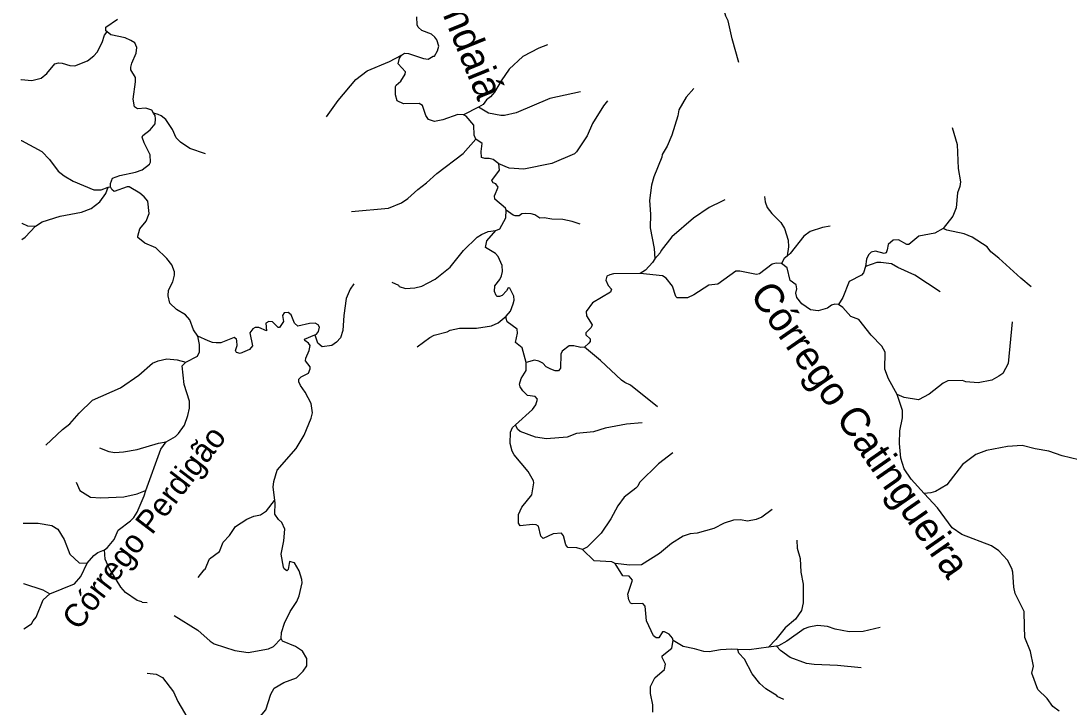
# Model space of a CAD drawing. Extents: x 393 to 446.6, y 8175.5 to 8231.
# Drawn here: x 393.18 to 400.42, y 8189.65 to 8194.39 of the extents above; entities that cross this region are included whole.
import ezdxf
from ezdxf.enums import TextEntityAlignment as Align

# ---------------------------------------------------------------- set-up
doc = ezdxf.new("R2010")
doc.units = 0
doc.header["$LTSCALE"] = 0.064
doc.linetypes.add('LONG_DASHED', pattern=[7.5, 6, -1.5])
doc.layers.add('61', color=7, linetype='Continuous')
doc.layers.add('7', color=7, linetype='Continuous', lineweight=25)
doc.layers.add('9', color=7, linetype='LONG_DASHED', lineweight=25)

msp = doc.modelspace()

# ---------------------------------------------------------------- linework, layer by layer
at = {"layer": '7'}
for p, q in [((396.3375, 8193.7957), (396.2359, 8193.7427)), ((393.7808, 8193.2408), (393.7972, 8193.2449)), ((398.3961, 8190.0715), (398.3408, 8190.0636))]:
    msp.add_line(p, q, dxfattribs=at)
for points in [[(393.7727, 8194.3151), (393.7638, 8194.322), (393.7638, 8194.3464), (393.8441, 8194.4029)], [(395.8073, 8194.1538), (395.8271, 8194.1666), (395.8561, 8194.1655), (395.9595, 8194.1316), (395.9918, 8194.1267), (396.0257, 8194.1461), (396.0354, 8194.1461), (396.0564, 8194.1833), (396.0644, 8194.2156), (396.0499, 8194.2608), (396.037, 8194.2785), (396.0128, 8194.2995), (395.9482, 8194.3254), (395.9207, 8194.348), (395.9159, 8194.3625), (395.9126, 8194.419)], [(393.1782, 8193.9868), (393.1792, 8193.9867), (393.18, 8193.9866), (393.2531, 8193.9782), (393.3177, 8193.9959), (393.3564, 8194.0282), (393.4114, 8194.0944), (393.4372, 8194.1009), (393.463, 8194.0993), (393.5147, 8194.0831), (393.5502, 8194.0799), (393.6374, 8194.1138), (393.6826, 8194.1493), (393.7052, 8194.1752), (393.7391, 8194.2414), (393.7553, 8194.2931), (393.7708, 8194.3127), (393.7727, 8194.3151)], [(394.0935, 8193.7537), (394.082, 8193.7727), (394.0411, 8193.7876), (393.983, 8193.7828), (393.962, 8193.7973), (393.9523, 8193.8506), (393.97, 8193.9701), (393.9684, 8193.9992), (393.9377, 8194.0525), (393.9377, 8194.0702), (393.9442, 8194.0993), (393.9749, 8194.1671), (393.9797, 8194.2059), (393.9636, 8194.2382), (393.9378, 8194.2559), (393.899, 8194.2737), (393.7989, 8194.2947), (393.7727, 8194.3151)], [(396.8147, 8194.2256), (396.7556, 8194.2026), (396.6442, 8194.1445), (396.5505, 8194.0573), (396.494, 8193.9766), (396.4487, 8193.8991), (396.4221, 8193.8655), (396.3942, 8193.8446), (396.3709, 8193.8132), (396.3375, 8193.7957)], [(395.289, 8193.7272), (395.3701, 8193.8409), (395.4912, 8193.9863), (395.5687, 8194.046), (395.7237, 8194.1106), (395.8073, 8194.1538)], [(396.2359, 8193.7427), (396.1951, 8193.7439), (396.0919, 8193.7069), (396.0337, 8193.6956), (395.9934, 8193.7101), (395.974, 8193.7376), (395.9514, 8193.807), (395.9288, 8193.8199), (395.8206, 8193.8183), (395.777, 8193.8377), (395.7657, 8193.8797), (395.7657, 8193.9378), (395.7689, 8193.9475), (395.8012, 8193.9749), (395.8319, 8194.0218), (395.8351, 8194.0396), (395.7835, 8194.0945), (395.7933, 8194.1329), (395.8073, 8194.1538)], [(397.0442, 8193.9016), (396.8315, 8193.8554), (396.599, 8193.7553), (396.5182, 8193.7359), (396.4923, 8193.7359), (396.4085, 8193.7537), (396.3394, 8193.7946), (396.3375, 8193.7957)], [(397.2303, 8193.838), (397.2023, 8193.8031), (397.1254, 8193.6811), (397.0882, 8193.5955), (397.0155, 8193.4857), (397.001, 8193.4727), (396.8444, 8193.4049), (396.6506, 8193.3662), (396.5505, 8193.3742), (396.4781, 8193.4036)], [(393.7972, 8193.2449), (393.796, 8193.267), (393.81, 8193.3031), (393.8602, 8193.3226), (393.9701, 8193.3452), (394.0153, 8193.3613), (394.0669, 8193.4001), (394.0734, 8193.4146), (394.0701, 8193.4663), (394.0282, 8193.5471), (394.0152, 8193.5874), (394.0201, 8193.5987), (394.0702, 8193.6375), (394.1057, 8193.6794), (394.1073, 8193.715), (394.1041, 8193.736), (394.0935, 8193.7537)], [(394.4537, 8193.4727), (394.3447, 8193.5099), (394.2801, 8193.5519), (394.251, 8193.5826), (394.2252, 8193.6407), (394.1783, 8193.7085), (394.1461, 8193.7343), (394.1251, 8193.7441), (394.096, 8193.7529), (394.0935, 8193.7537)], [(396.3196, 8193.5729), (396.3079, 8193.6002), (396.3067, 8193.6698), (396.2534, 8193.7328), (396.2359, 8193.7427)], [(393.1803, 8193.5652), (393.1812, 8193.5647), (393.3225, 8193.4873), (393.3742, 8193.434), (393.4355, 8193.3533), (393.4759, 8193.321), (393.5389, 8193.2838), (393.6826, 8193.2224), (393.7311, 8193.2224), (393.7808, 8193.2408)], [(395.4604, 8193.0732), (395.7173, 8193.0965), (395.8077, 8193.1336), (395.8513, 8193.1627), (395.9191, 8193.2257), (395.9805, 8193.2709), (396.0499, 8193.3371), (396.2324, 8193.4743), (396.3196, 8193.5729)], [(396.4781, 8193.4036), (396.439, 8193.434), (396.4116, 8193.4405), (396.3826, 8193.4388), (396.3583, 8193.4469), (396.3567, 8193.4889), (396.3648, 8193.5438), (396.3196, 8193.5729)], [(396.5298, 8193.0832), (396.5252, 8193.0972), (396.4504, 8193.1595), (396.4488, 8193.1821), (396.4746, 8193.2418), (396.4585, 8193.2645), (396.4407, 8193.2725), (396.431, 8193.287), (396.4843, 8193.3597), (396.4781, 8193.4036)], [(393.2796, 8192.9735), (393.3242, 8193.0012), (393.4501, 8193.0416), (393.5954, 8193.069), (393.6633, 8193.0933), (393.723, 8193.1401), (393.7633, 8193.1983), (393.7808, 8193.2408)], [(394.3993, 8192.2132), (394.3689, 8192.2552), (394.3447, 8192.3263), (394.3156, 8192.3586), (394.2526, 8192.3957), (394.2058, 8192.4393), (394.1945, 8192.491), (394.1977, 8192.5297), (394.2268, 8192.5879), (394.2381, 8192.6331), (394.2381, 8192.6557), (394.2203, 8192.7041), (394.1864, 8192.7493), (394.1089, 8192.822), (394.0347, 8192.8559), (393.9862, 8192.893), (393.9846, 8192.9043), (393.9991, 8192.9528), (394.0427, 8193.0077), (394.0637, 8193.0594), (394.0556, 8193.145), (394.0298, 8193.1756), (393.9991, 8193.1998), (393.9249, 8193.2434), (393.9119, 8193.2451), (393.8215, 8193.2128), (393.8053, 8193.2257), (393.7972, 8193.2449)], [(396.4581, 8192.943), (396.4859, 8192.9544), (396.5263, 8193.0303), (396.5298, 8193.0832)], [(397.0417, 8192.9853), (396.9865, 8193.0045), (396.9219, 8193.0174), (396.8444, 8193.0206), (396.7927, 8193.0303), (396.762, 8193.0271), (396.7281, 8193.0513), (396.7023, 8193.0577), (396.6635, 8193.061), (396.6377, 8193.0577), (396.6183, 8193.0448), (396.5925, 8193.0448), (396.5779, 8193.048), (396.5298, 8193.0832)], [(393.1831, 8192.9933), (393.184, 8192.9928), (393.224, 8192.9738), (393.2796, 8192.9735)], [(393.1837, 8192.88), (393.1846, 8192.8806), (393.2074, 8192.8965), (393.2796, 8192.9735)], [(395.7393, 8192.5848), (395.7851, 8192.5636), (395.7916, 8192.5555), (395.8335, 8192.5426), (395.8981, 8192.5459), (395.9466, 8192.5588), (395.9918, 8192.5797), (396.0402, 8192.6056), (396.1419, 8192.6896), (396.2356, 8192.8043), (396.3293, 8192.8962), (396.3583, 8192.9156), (396.4052, 8192.935), (396.4581, 8192.943)], [(396.5299, 8192.3508), (396.5585, 8192.386), (396.5779, 8192.4361), (396.5844, 8192.4619), (396.5828, 8192.4878), (396.5553, 8192.5443), (396.5424, 8192.5459), (396.5327, 8192.5265), (396.502, 8192.4942), (396.4827, 8192.4861), (396.4665, 8192.4861), (396.4601, 8192.4942), (396.4488, 8192.52), (396.452, 8192.5604), (396.4859, 8192.604), (396.4972, 8192.6282), (396.5037, 8192.6589), (396.502, 8192.7009), (396.4746, 8192.7623), (396.4552, 8192.7832), (396.3858, 8192.8252), (396.3954, 8192.8704), (396.4581, 8192.943)], [(395.4782, 8192.5733), (395.4524, 8192.5378), (395.4253, 8192.4722), (395.425, 8192.4716), (395.4088, 8192.3553), (395.4023, 8192.252), (395.3862, 8192.2019), (395.3588, 8192.1712), (395.3265, 8192.1486), (395.2587, 8192.1389), (395.228, 8192.1631), (395.2094, 8192.2192), (395.2083, 8192.2224)], [(395.2083, 8192.2224), (395.2199, 8192.2273), (395.2344, 8192.2455), (395.2409, 8192.2746), (395.2312, 8192.2907), (395.2102, 8192.302), (395.1715, 8192.3004), (395.0907, 8192.281), (395.0681, 8192.302), (395.0455, 8192.3602), (395.0229, 8192.3763), (394.9954, 8192.3731), (394.9857, 8192.3553), (394.9906, 8192.3134), (394.9648, 8192.2729), (394.9551, 8192.2729), (394.9163, 8192.3117), (394.8905, 8192.3133), (394.8695, 8192.302), (394.8743, 8192.2487), (394.8211, 8192.2729), (394.7968, 8192.2713), (394.7791, 8192.2633), (394.7597, 8192.2358), (394.7774, 8192.1454), (394.7564, 8192.1212), (394.6919, 8192.0921), (394.666, 8192.0985), (394.6595, 8192.1131), (394.6709, 8192.1486), (394.6692, 8192.1809), (394.6676, 8192.1922), (394.6515, 8192.2035), (394.5579, 8192.1664), (394.5256, 8192.1664), (394.5013, 8192.168), (394.4707, 8192.1793), (394.3993, 8192.2132)], [(395.9158, 8192.1396), (396.0015, 8192.2035), (396.0321, 8192.2197), (396.121, 8192.2423), (396.1436, 8192.2536), (396.2082, 8192.2665), (396.3244, 8192.2681), (396.4278, 8192.2843), (396.4746, 8192.3052), (396.5299, 8192.3508)], [(396.6676, 8192.0303), (396.6393, 8192.1308), (396.5941, 8192.1696), (396.607, 8192.2326), (396.6054, 8192.2617), (396.5369, 8192.3124), (396.5287, 8192.3333), (396.5299, 8192.3508)], [(394.9311, 8191.0781), (394.9211, 8191.1701), (394.9244, 8191.2088), (394.947, 8191.2863), (395.0794, 8191.4365), (395.1343, 8191.5286), (395.1827, 8191.6448), (395.1908, 8191.6836), (395.1827, 8191.7482), (395.1408, 8191.8257), (395.1085, 8191.8709), (395.0972, 8191.8967), (395.0972, 8191.9161), (395.1133, 8191.9322), (395.1634, 8191.9565), (395.1763, 8191.9872), (395.1763, 8192.0001), (395.144, 8192.0421), (395.1456, 8192.0614), (395.1698, 8192.1131), (395.1763, 8192.147), (395.165, 8192.1632), (395.1392, 8192.1825), (395.1375, 8192.1922), (395.2083, 8192.2224)], [(396.5949, 8191.6), (396.7119, 8191.7062), (396.7346, 8191.7368), (396.7459, 8191.7772), (396.7297, 8191.795), (396.6764, 8191.803), (396.6442, 8191.8337), (396.6264, 8191.8612), (396.6215, 8191.8806), (396.6328, 8191.9193), (396.6684, 8191.9742), (396.6676, 8192.0303)], [(397.0559, 8190.7372), (397.0188, 8190.7502), (396.9558, 8190.7518), (396.9429, 8190.7712), (396.9267, 8190.8326), (396.9122, 8190.8503), (396.8541, 8190.8471), (396.7863, 8190.8148), (396.7685, 8190.8309), (396.7524, 8190.8988), (396.7378, 8190.9084), (396.712, 8190.9117), (396.6264, 8190.902), (396.6151, 8190.9198), (396.6151, 8190.9795), (396.6377, 8191.0312), (396.7071, 8191.1167), (396.72, 8191.1991), (396.7184, 8191.2121), (396.6813, 8191.2767), (396.586, 8191.3929), (396.5715, 8191.4188), (396.5569, 8191.4704), (396.5602, 8191.5479), (396.5741, 8191.5811), (396.5949, 8191.6)], [(397.4681, 8191.6138), (397.3611, 8191.6044), (397.2126, 8191.577), (397.1318, 8191.5511), (397.0156, 8191.5398), (396.951, 8191.514), (396.8089, 8191.5027), (396.7314, 8191.514), (396.6264, 8191.5527), (396.6086, 8191.5705), (396.5951, 8191.5997), (396.5949, 8191.6)], [(397.6813, 8191.4065), (397.5823, 8191.3299), (397.4499, 8191.2007), (397.4386, 8191.1749), (397.4257, 8191.162), (397.345, 8191.1006), (397.3013, 8191.0409), (397.2529, 8190.9505), (397.1851, 8190.8519), (397.0882, 8190.755), (397.0559, 8190.7372)], [(394.4023, 8190.544), (394.4432, 8190.5984), (394.4512, 8190.6017), (394.4803, 8190.6727), (394.5498, 8190.7244), (394.574, 8190.789), (394.6176, 8190.8358), (394.6595, 8190.8972), (394.7387, 8190.949), (394.7865, 8190.9688), (394.8331, 8190.9769), (394.8751, 8191.0066), (394.9295, 8191.076), (394.9311, 8191.0781)], [(394.9753, 8190.1239), (394.9777, 8190.1657), (394.9986, 8190.2303), (395.0374, 8190.311), (395.0826, 8190.3788), (395.1004, 8190.4176), (395.1198, 8190.508), (395.1182, 8190.5322), (395.0988, 8190.592), (395.0681, 8190.6453), (395.0326, 8190.6565), (395.0229, 8190.6), (395.0148, 8190.5919), (394.997, 8190.6049), (394.9922, 8190.6162), (394.9744, 8190.705), (394.9938, 8190.7987), (395.0003, 8190.8778), (394.9793, 8190.9246), (394.9567, 8190.9456), (394.9325, 8190.9828), (394.933, 8191.0609), (394.9311, 8191.0781)], [(398.3679, 8191.0147), (398.2945, 8190.9617), (398.2573, 8190.9456), (398.1976, 8190.9343), (398.1492, 8190.944), (398.1007, 8190.9407), (398.0361, 8190.9197), (397.9651, 8190.8826), (397.8488, 8190.8519), (397.8004, 8190.8471), (397.7519, 8190.8309), (397.6712, 8190.7809), (397.5888, 8190.7114), (397.4645, 8190.6323), (397.3837, 8190.6307), (397.2816, 8190.6411)], [(398.5363, 8190.803), (398.5399, 8190.747), (398.5593, 8190.676), (398.5657, 8190.5823), (398.5819, 8190.4983), (398.5819, 8190.3691), (398.569, 8190.3175), (398.527, 8190.2577), (398.456, 8190.1979), (398.3913, 8190.1156), (398.3409, 8190.0637), (398.3408, 8190.0636)], [(397.2816, 8190.6411), (397.2606, 8190.6527), (397.1367, 8190.6598), (397.0559, 8190.7372)], [(397.6821, 8190.1104), (397.6786, 8190.1256), (397.6566, 8190.1543), (397.6227, 8190.1689), (397.6098, 8190.1689), (397.5839, 8190.1285), (397.5646, 8190.1285), (397.5468, 8190.1414), (397.5, 8190.2464), (397.4903, 8190.3465), (397.4725, 8190.3643), (397.3999, 8190.3626), (397.3886, 8190.3675), (397.3772, 8190.3917), (397.3708, 8190.4305), (397.4031, 8190.5258), (397.3789, 8190.5532), (397.3353, 8190.5564), (397.2816, 8190.6411)], [(394.237, 8190.2832), (394.3996, 8190.1818), (394.4852, 8190.1043), (394.5126, 8190.0865), (394.6547, 8190.0397), (394.7484, 8190.0268), (394.8873, 8190.051), (394.9228, 8190.0671), (394.9753, 8190.1239)], [(399.1118, 8190.1984), (398.9953, 8190.1721), (398.8984, 8190.1705), (398.8015, 8190.1883), (398.7482, 8190.206), (398.6804, 8190.2141), (398.6207, 8190.2028), (398.5884, 8190.1899), (398.4689, 8190.1059), (398.4107, 8190.0736), (398.3961, 8190.0715)], [(394.5494, 8189.4886), (394.6076, 8189.4979), (394.658, 8189.5181), (394.7161, 8189.5569), (394.7355, 8189.5601), (394.7872, 8189.5536), (394.8195, 8189.5698), (394.8695, 8189.6296), (394.905, 8189.7394), (394.926, 8189.7797), (394.9938, 8189.8201), (395.081, 8189.8524), (395.1278, 8189.8976), (395.1521, 8189.9347), (395.1521, 8189.9848), (395.123, 8190.0365), (395.0746, 8190.0671), (394.9857, 8190.1059), (394.9753, 8190.1239)], [(397.5436, 8189.6134), (397.5436, 8189.6651), (397.5274, 8189.7426), (397.5258, 8189.791), (397.5565, 8189.8524), (397.6243, 8189.9089), (397.6308, 8189.9461), (397.6065, 8189.9913), (397.6065, 8190.0042), (397.6728, 8190.0575), (397.6821, 8190.1104)], [(398.1302, 8190.0472), (398.0889, 8190.0486), (398.0103, 8190.0445), (397.9328, 8190.0316), (397.894, 8190.0332), (397.8294, 8190.0526), (397.7519, 8190.0671), (397.6821, 8190.1104)], [(398.3408, 8190.0636), (398.2073, 8190.0445), (398.1302, 8190.0472)], [(398.9819, 8189.9205), (398.8177, 8189.9363), (398.6562, 8189.9428), (398.6045, 8189.9509), (398.4915, 8189.9912), (398.4237, 8190.0413), (398.3968, 8190.0707), (398.3961, 8190.0715)], [(398.4477, 8189.7024), (398.4023, 8189.7222), (398.4011, 8189.7281), (398.3236, 8189.7749), (398.2815, 8189.812), (398.2299, 8189.8782), (398.1766, 8189.9816), (398.1378, 8190.0219), (398.1308, 8190.0451), (398.1302, 8190.0472)], [(394.0509, 8189.8833), (394.1122, 8189.8766), (394.1558, 8189.854), (394.2316, 8189.7539), (394.2623, 8189.6877), (394.3463, 8189.544), (394.3833, 8189.5037)]]:
    msp.add_lwpolyline(points, dxfattribs=at)
at = {"layer": '9'}
for points in [[(398.1378, 8194.1043), (398.091, 8194.2656), (398.0619, 8194.39), (398.0474, 8194.4239), (398.0151, 8194.5418), (397.9828, 8194.6225), (397.9699, 8194.6903), (397.8988, 8194.8873), (397.8762, 8194.9875), (397.8585, 8195.178), (397.8746, 8195.4138), (398.0167, 8195.8061), (398.133, 8196.0177), (398.2212, 8196.1567), (398.2702, 8196.2341), (398.3445, 8196.3972), (398.3575, 8196.4375), (398.4195, 8196.5647)], [(397.8254, 8193.9244), (397.7729, 8193.8636), (397.7228, 8193.7764), (397.7164, 8193.7344), (397.6744, 8193.602), (397.6421, 8193.526), (397.6066, 8193.4679), (397.6049, 8193.4501), (397.55, 8193.3129), (397.5339, 8193.2564), (397.5194, 8193.1498), (397.5258, 8193.0545), (397.5242, 8192.9609), (397.5517, 8192.8172), (397.5565, 8192.7477)], [(399.6093, 8193.6546), (399.6445, 8193.5357), (399.6509, 8193.371), (399.667, 8193.279), (399.6638, 8193.2467), (399.6461, 8193.2031), (399.638, 8193.0981), (399.6154, 8193.0416), (399.5473, 8192.9556)], [(398.315, 8193.1774), (398.3187, 8193.1401), (398.3332, 8193.1014), (398.3639, 8193.061), (398.4269, 8192.998), (398.4527, 8192.956), (398.4785, 8192.8753), (398.4801, 8192.8301), (398.4705, 8192.7673), (398.4702, 8192.7655)], [(398.0408, 8193.154), (398.0221, 8193.1449), (397.9328, 8193.1013), (397.8246, 8193.0287), (397.6728, 8192.8995), (397.6001, 8192.8042), (397.5936, 8192.7881), (397.5565, 8192.7477)], [(398.7676, 8192.972), (398.7139, 8192.9638), (398.6287, 8192.9358), (398.5855, 8192.9043), (398.4921, 8192.783), (398.4702, 8192.7655)], [(399.5473, 8192.9556), (399.491, 8192.9237), (399.3796, 8192.9043), (399.3102, 8192.8462), (399.2968, 8192.8468), (399.2396, 8192.8771), (399.2034, 8192.8759), (399.1681, 8192.8446), (399.1624, 8192.8094), (399.1538, 8192.7892), (399.1413, 8192.7837), (399.0817, 8192.8), (399.0514, 8192.7919), (399.0327, 8192.7744), (399.0175, 8192.744), (399.0117, 8192.6927)], [(400.1557, 8192.5532), (400.0837, 8192.612), (399.9335, 8192.7509), (399.877, 8192.7945), (399.8527, 8192.8301), (399.7478, 8192.8962), (399.6929, 8192.9189), (399.5734, 8192.9447), (399.5473, 8192.9556)], [(397.5565, 8192.7477), (397.5412, 8192.7218), (397.491, 8192.6682), (397.455, 8192.646)], [(398.4702, 8192.7655), (398.4507, 8192.7498), (398.4311, 8192.7146)], [(398.4311, 8192.7146), (398.3938, 8192.717), (398.3681, 8192.7088), (398.2788, 8192.644), (398.259, 8192.6395), (398.1427, 8192.6621), (398.1169, 8192.6605), (397.9925, 8192.5717), (397.9295, 8192.5636), (397.8262, 8192.4974), (397.7826, 8192.4764), (397.7099, 8192.4764), (397.7018, 8192.4861), (397.6776, 8192.5572), (397.634, 8192.6137), (397.6098, 8192.6282), (397.455, 8192.646)], [(398.8251, 8192.4318), (398.7994, 8192.4329), (398.776, 8192.4259), (398.7492, 8192.4061), (398.6856, 8192.388), (398.6307, 8192.395), (398.5717, 8192.4352), (398.5367, 8192.4784), (398.5312, 8192.5087), (398.5362, 8192.5391), (398.5332, 8192.5659), (398.4912, 8192.5962), (398.4708, 8192.6843), (398.4311, 8192.7146)], [(399.0117, 8192.6927), (398.9977, 8192.6507), (398.9849, 8192.6332), (398.8985, 8192.5901), (398.8559, 8192.4787), (398.8251, 8192.4318)], [(399.5265, 8192.5195), (399.3522, 8192.6331), (399.2343, 8192.6863), (399.1907, 8192.7122), (399.118, 8192.7219), (399.089, 8192.7203), (399.0117, 8192.6927)], [(397.455, 8192.646), (397.2707, 8192.6427), (397.2449, 8192.6363), (397.2239, 8192.6266), (397.2175, 8192.6004), (397.2338, 8192.5619), (397.2561, 8192.5362), (397.2513, 8192.5152), (397.127, 8192.4425), (397.0817, 8192.3828), (397.0834, 8192.3521), (397.1227, 8192.2904), (397.1157, 8192.2717), (397.0807, 8192.2355), (397.0807, 8192.2204), (397.1087, 8192.1935), (397.1087, 8192.1749), (397.1017, 8192.1632), (397.0713, 8192.1364)], [(399.2314, 8191.8102), (399.1696, 8191.9175), (399.1454, 8191.9839), (399.1471, 8192.1018), (399.1245, 8192.1438), (399.0502, 8192.2197), (398.9662, 8192.3278), (398.9097, 8192.3472), (398.8554, 8192.4108), (398.8251, 8192.4318)], [(400.0257, 8192.3123), (399.9981, 8192.0227), (399.9593, 8191.9548), (399.9319, 8191.9355), (399.8834, 8191.908), (399.7898, 8191.8902), (399.7058, 8191.8967), (399.6816, 8191.9064), (399.5799, 8191.9032), (399.5476, 8191.887), (399.4523, 8191.8111), (399.378, 8191.7724), (399.2795, 8191.7885), (399.2314, 8191.8102)], [(394.3176, 8192.0335), (394.397, 8192.0744), (394.411, 8192.1047), (394.4121, 8192.1549), (394.3993, 8192.2132)], [(397.0713, 8192.1364), (397.0456, 8192.1329), (396.9962, 8192.1454), (396.965, 8192.1457), (396.9159, 8192.1084), (396.9078, 8192.0874), (396.9054, 8191.9906), (396.8914, 8191.9731), (396.8692, 8191.9719), (396.8377, 8191.9836), (396.8062, 8192.0011), (396.784, 8192.0267), (396.7549, 8192.0407), (396.7257, 8192.0454), (396.6676, 8192.0303)], [(397.5754, 8191.7237), (397.3886, 8191.8741), (397.3482, 8191.8918), (397.3272, 8191.908), (397.1819, 8192.0437), (397.0713, 8192.1364)], [(393.3494, 8191.4585), (393.4649, 8191.567), (393.5147, 8191.606), (393.5793, 8191.6803), (393.6713, 8191.7692), (393.8651, 8191.8564), (393.9926, 8191.9435), (394.0863, 8192.0259), (394.1251, 8192.042), (394.1848, 8192.055), (394.2575, 8192.0485), (394.3176, 8192.0335)], [(394.1823, 8191.4811), (394.2465, 8191.5196), (394.2655, 8191.5399), (394.3075, 8191.598), (394.3318, 8191.6642), (394.3414, 8191.7159), (394.3415, 8191.7627), (394.3059, 8191.8774), (394.2914, 8192.0065), (394.3176, 8192.0335)], [(399.4175, 8191.1249), (399.3263, 8191.2234), (399.2779, 8191.296), (399.2552, 8191.3703), (399.2472, 8191.4704), (399.2488, 8191.5576), (399.2666, 8191.6481), (399.2666, 8191.6981), (399.2314, 8191.8102)], [(393.7202, 8191.4399), (393.786, 8191.4155), (393.8263, 8191.4074), (393.8861, 8191.4123), (393.9798, 8191.43), (394.1283, 8191.472), (394.1823, 8191.4811)], [(394.0418, 8191.1466), (394.1444, 8191.4317), (394.1823, 8191.4811)], [(400.8447, 8191.2597), (400.5552, 8191.3331), (400.4857, 8191.359), (400.3711, 8191.3848), (400.2791, 8191.4188), (400.1838, 8191.4332), (400.0934, 8191.4575), (399.9933, 8191.451), (399.8479, 8191.422), (399.7736, 8191.3945), (399.6816, 8191.3267), (399.5734, 8191.1862), (399.4943, 8191.1394), (399.4636, 8191.1297), (399.4175, 8191.1249)], [(393.5598, 8191.2042), (393.5841, 8191.1458), (393.6584, 8191.1006), (393.7295, 8191.0958), (393.8877, 8191.1023), (393.9798, 8191.1232), (394.039, 8191.1455), (394.0418, 8191.1466)], [(393.7541, 8190.7352), (393.7763, 8190.7527), (393.8229, 8190.8075), (393.8506, 8190.8713), (393.9345, 8190.9375), (393.9571, 8190.9601), (393.9814, 8190.9973), (394.0282, 8191.1087), (394.0418, 8191.1466)], [(400.3485, 8189.6214), (400.3049, 8189.6538), (400.2661, 8189.7087), (400.2015, 8189.7717), (400.1595, 8189.8847), (400.1725, 8189.9315), (400.1515, 8190.0333), (400.1127, 8190.1302), (400.1107, 8190.2072), (400.1079, 8190.311), (400.0465, 8190.4337), (400.0368, 8190.4789), (400.0287, 8190.5823), (400.0223, 8190.6081), (399.9933, 8190.6646), (399.9335, 8190.7292), (399.8818, 8190.7648), (399.6768, 8190.8422), (399.6105, 8190.8875), (399.5088, 8191.0263), (399.4175, 8191.1249)], [(393.1933, 8190.9192), (393.1941, 8190.9193), (393.2967, 8190.9214), (393.392, 8190.9036), (393.434, 8190.8778), (393.4775, 8190.8084), (393.5147, 8190.7066), (393.5793, 8190.6452), (393.6345, 8190.6437)], [(393.6345, 8190.6437), (393.6823, 8190.6973), (393.7103, 8190.7183), (393.7541, 8190.7352)], [(394.0498, 8190.3699), (394.0153, 8190.3723), (394.0137, 8190.3772), (393.9814, 8190.3869), (393.9006, 8190.4402), (393.8683, 8190.4773), (393.786, 8190.6132), (393.7592, 8190.6715), (393.7541, 8190.7352)], [(393.3772, 8190.4324), (393.5486, 8190.5016), (393.5922, 8190.5516), (393.6345, 8190.6437)], [(393.1954, 8190.5036), (393.1962, 8190.5033), (393.329, 8190.4587), (393.3772, 8190.4324)], [(393.1969, 8190.1902), (393.1977, 8190.1907), (393.2515, 8190.2254), (393.2624, 8190.246), (393.2838, 8190.2706), (393.3306, 8190.3917), (393.3772, 8190.4324)]]:
    msp.add_lwpolyline(points, dxfattribs=at)

# ---------------------------------------------------------------- texts
at = {"layer": '61'}
for s, height, rotation, p in [('Córrego Indaiá', 0.2, 292.094, (396.0029, 8194.6493)), ('Córrego Catingueira', 0.2, 304.811, (398.895, 8191.5116)), ('Córrego Perdigão', 0.16, 52.539, (394.0906, 8190.8428))]:
    msp.add_text(s, height=height, rotation=rotation, dxfattribs=at).set_placement(p, align=Align.CENTER)

doc.saveas('drawing.dxf')
